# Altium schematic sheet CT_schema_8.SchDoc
size 226 x 144 mm
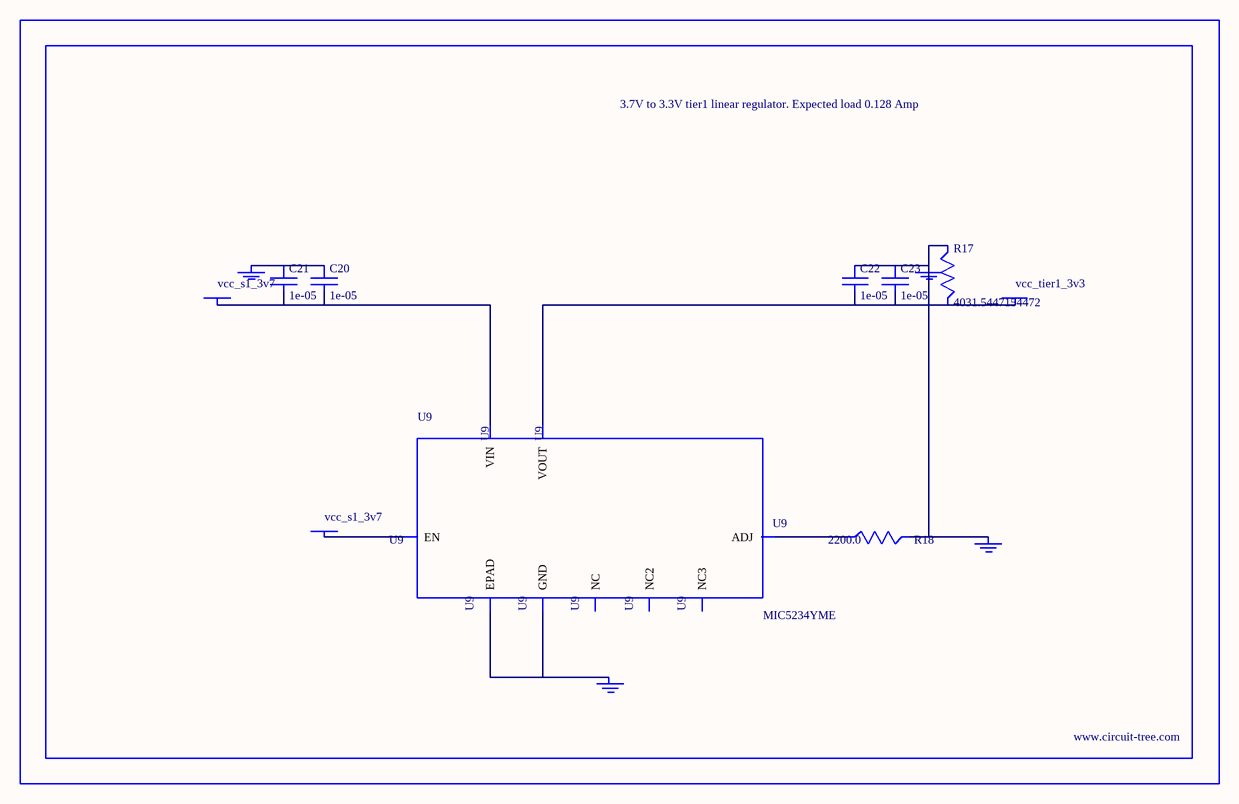
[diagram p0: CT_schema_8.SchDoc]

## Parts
BORDER7  (no value)
C20  1e-05  [C1210]
C21  1e-05  [C1210]
C22  1e-05  [C1210]
C23  1e-05  [C1210]
GND_INSTANCE_7_0  (no value)
GND_INSTANCE_7_1  (no value)
GND_INSTANCE_7_2  (no value)
GND_INSTANCE_7_3  (no value)
POWER_INSTANCE_7_0  vcc_tier1_3v3
POWER_INSTANCE_7_1  vcc_s1_3v7
POWER_INSTANCE_7_2  vcc_s1_3v7
R17  4031.5447154472  [R0603]
R18  2200.0  [R0603]
U9  MIC5234YME  [SOIC-8_EP]

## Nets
NetC20_1: C20.1 C21.1 GND_INSTANCE_7_3.0(GND)
NetC20_2: C20.2 C21.2 POWER_INSTANCE_7_2.0(PWR) U9.8(VIN)
NetC22_1: C22.1 C23.1 GND_INSTANCE_7_0.0(GND) GND_INSTANCE_7_1.0(GND) R17.1 R18.2
NetC22_2: C22.2 C23.2 POWER_INSTANCE_7_0.0(PWR) R17.2 U9.1(VOUT)
NetGND_INSTANCE_7_2_0: GND_INSTANCE_7_2.0(GND) U9.7(GND) U9.EPAD
NetPOWER_INSTANCE_7_1_0: POWER_INSTANCE_7_1.0(PWR) U9.5(EN)
NetR18_1: R18.1 U9.4(ADJ)

Not connected (* = marked no-connect by the designer): U9 2(NC) 3(NC2) 6(NC3)

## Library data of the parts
BORDER7 = BORDER_PAGE7
C20-C23 = C1210C106K5PACTU
GND_INSTANCE_7_0-GND_INSTANCE_7_3 = GND
POWER_INSTANCE_7_0-POWER_INSTANCE_7_2 = PWR
R17 = R17
R18 = RC0603JR-072K2L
